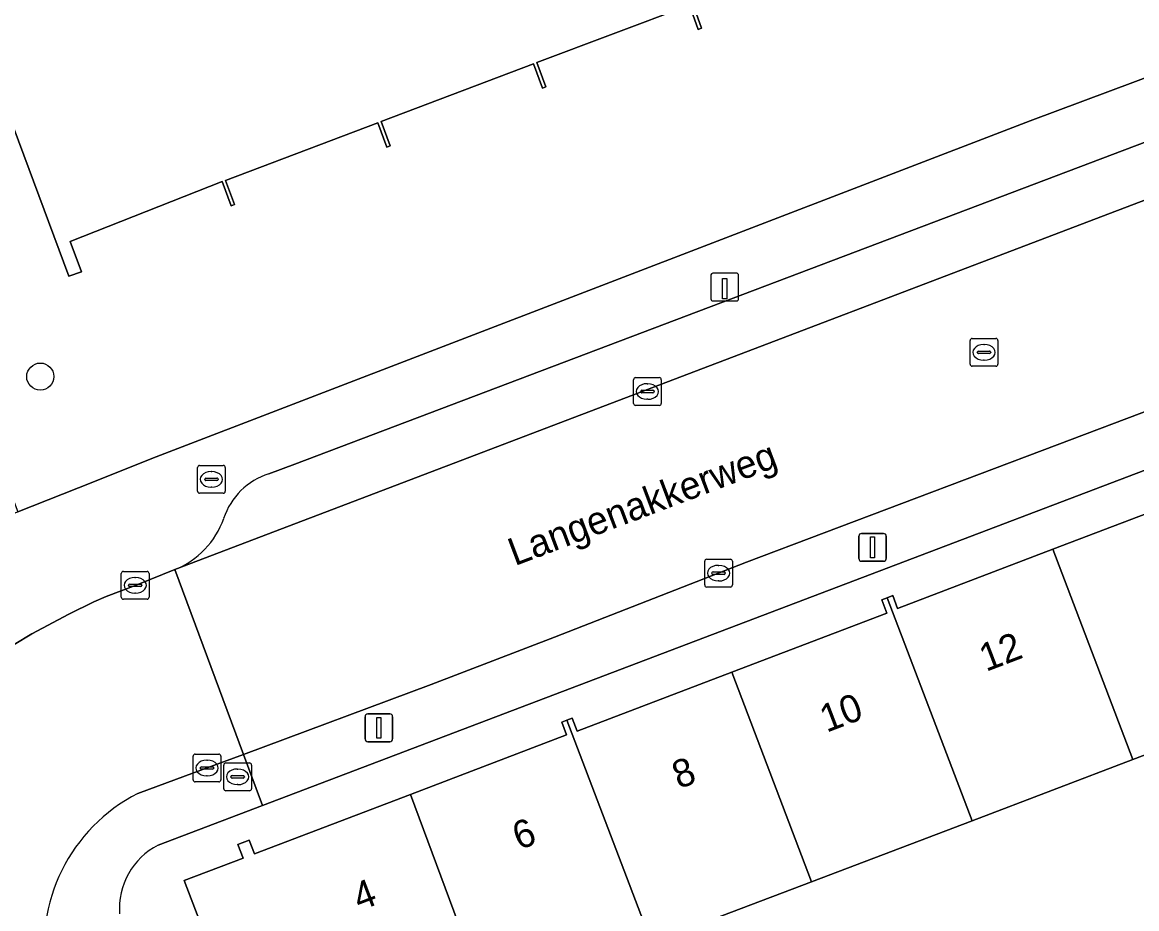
# Model space of a CAD drawing. Extents: x 159262 to 160143, y 383399 to 384319.
# Drawn here: x 159354.79 to 159394.93, y 383878.17 to 383910.07 of the extents above; entities that cross this region are included whole.
import ezdxf

# ---------------------------------------------------------------- set-up
doc = ezdxf.new("R2010")
doc.units = 0
for name, color, linetype in [('IMGEO_Boom', 7, 'Continuous'), ('IMGEO_Brandkraan', 7, 'Continuous'), ('IMGEO_Erf', 7, 'Continuous'), ('IMGEO_Kolk', 7, 'Continuous'), ('IMGEO_Laadpaal', 7, 'Continuous'), ('IMGEO_Lichtmast', 7, 'Continuous'), ('IMGEO_Openbare_ruimte_label', 7, 'Continuous'), ('IMGEO_Pand', 7, 'Continuous'), ('IMGEO_Pand_nummerreeks', 7, 'Continuous'), ('IMGEO_Parkeervlak_open', 7, 'Continuous'), ('IMGEO_Rijbaan_lokaal_open', 7, 'Continuous'), ('IMGEO_Rioolput', 7, 'Continuous'), ('IMGEO_Voetpad_open', 7, 'Continuous')]:
    doc.layers.add(name, color=color, linetype=linetype)

msp = doc.modelspace()

# ---------------------------------------------------------------- linework, layer by layer
at = {"layer": 'IMGEO_Boom'}
msp.add_circle((159355.441, 383897.316), 0.489, dxfattribs=at)
at = {"layer": 'IMGEO_Brandkraan'}
for p, q in [((159361.103, 383893.192), (159361.103, 383894.044)), ((159361.178, 383894.118), (159362.03, 383894.118)), ((159361.591, 383893.898), (159361.616, 383893.898)), ((159362.104, 383894.044), (159362.104, 383893.192)), ((159361.362, 383893.612), (159361.362, 383893.624)), ((159361.8, 383893.575), (159361.402, 383893.575)), ((159361.405, 383893.661), (159361.803, 383893.661)), ((159361.846, 383893.624), (159361.846, 383893.612)), ((159362.03, 383893.118), (159361.178, 383893.118)), ((159361.614, 383893.338), (159361.589, 383893.338)), ((159362.122, 383883.413), (159362.974, 383883.413)), ((159362.047, 383882.487), (159362.047, 383883.339)), ((159362.535, 383883.193), (159362.56, 383883.193)), ((159363.048, 383883.339), (159363.048, 383882.487)), ((159362.306, 383882.907), (159362.306, 383882.919)), ((159362.744, 383882.87), (159362.346, 383882.87)), ((159362.349, 383882.956), (159362.747, 383882.956)), ((159362.558, 383882.633), (159362.533, 383882.633)), ((159362.79, 383882.919), (159362.79, 383882.907)), ((159362.974, 383882.413), (159362.122, 383882.413))]:
    msp.add_line(p, q, dxfattribs=at)
for points in [[(159361.103, 383893.192), (159361.103, 383894.044)], [(159361.178, 383894.118), (159362.03, 383894.118)], [(159362.104, 383894.044), (159362.104, 383893.192)], [(159362.03, 383893.118), (159361.178, 383893.118)], [(159362.122, 383883.413), (159362.974, 383883.413)], [(159362.047, 383882.487), (159362.047, 383883.339)], [(159363.048, 383883.339), (159363.048, 383882.487)], [(159362.974, 383882.413), (159362.122, 383882.413)]]:
    msp.add_lwpolyline(points, dxfattribs=at)
for centre, radius, start, end in [((159361.18, 383894.042), 0.0765, 91.552, 178.448), ((159361.18, 383894.042), 0.0765, 91.552, 178.448), ((159362.028, 383894.042), 0.0765, 1.552, 88.448), ((159362.028, 383894.042), 0.0765, 1.552, 88.448), ((159361.402, 383893.621), 0.0403, 85.8775, 175.7526), ((159361.399, 383893.611), 0.0366, 178.938, 274.7102), ((159361.803, 383893.618), 0.043, 264.8664, 352.4533), ((159361.807, 383893.623), 0.0386, 1.7309, 96.639), ((159361.18, 383893.194), 0.0765, 181.552, 268.448), ((159361.18, 383893.194), 0.0765, 181.552, 268.448), ((159362.028, 383893.194), 0.0765, 271.552, 358.448), ((159362.028, 383893.194), 0.0765, 271.552, 358.448), ((159362.124, 383883.337), 0.0765, 91.552, 178.448), ((159362.124, 383883.337), 0.0765, 91.552, 178.448), ((159362.972, 383883.337), 0.0765, 1.552, 88.448), ((159362.972, 383883.337), 0.0765, 1.552, 88.448), ((159362.346, 383882.916), 0.0403, 85.8775, 175.7526), ((159362.343, 383882.906), 0.0366, 178.938, 274.7102), ((159362.747, 383882.913), 0.043, 264.8664, 352.4533), ((159362.751, 383882.918), 0.0386, 1.7309, 96.639), ((159362.124, 383882.489), 0.0765, 181.552, 268.448), ((159362.124, 383882.489), 0.0765, 181.552, 268.448), ((159362.972, 383882.489), 0.0765, 271.552, 358.448), ((159362.972, 383882.489), 0.0765, 271.552, 358.448)]:
    msp.add_arc(centre, radius, start, end, dxfattribs=at)
for centre, major_axis, ratio, start_param, end_param in [((159361.59, 383893.618), (-0.387, 0.002), 0.722429, 4.712389, 7.853982), ((159361.615, 383893.618), (-0.39, 0.002), 0.717154, 1.570796, 4.712389), ((159362.534, 383882.913), (-0.387, 0.002), 0.722429, 4.712389, 7.853982), ((159362.559, 383882.913), (-0.39, 0.002), 0.717154, 1.570796, 4.712389)]:
    msp.add_ellipse(centre, major_axis=major_axis, ratio=ratio, start_param=start_param, end_param=end_param, dxfattribs=at)
at = {"layer": 'IMGEO_Erf'}
for points in [[(159344.204, 383933.471), (159339.87, 383931.849), (159348.323, 383909.525), (159348.27, 383909.245), (159354.634, 383892.446), (159357.328, 383893.521), (159359.454, 383894.369), (159391.087, 383906.525), (159403.464, 383911.157), (159412.277, 383914.472)], [(159378.937, 383910.729), (159379.258, 383909.858), (159379.136, 383909.813), (159378.815, 383910.684), (159373.326, 383908.62), (159373.651, 383907.742), (159373.531, 383907.692), (159373.204, 383908.575), (159367.722, 383906.498), (159368.044, 383905.618), (159367.917, 383905.574), (159367.6, 383906.453), (159362.107, 383904.377), (159362.437, 383903.507), (159362.313, 383903.46), (159361.985, 383904.332), (159356.515, 383902.181), (159356.921, 383901.091), (159356.474, 383900.927), (159352.679, 383911.103)], [(159417.717, 383902.495), (159363.447, 383881.885), (159359.686, 383880.457)], [(159364.276, 383875.969), (159362.156, 383875.163), (159360.626, 383879.181), (159362.747, 383879.988), (159362.561, 383880.477), (159362.965, 383880.63), (159363.151, 383880.142), (159368.772, 383882.281), (159374.393, 383884.42), (159374.219, 383884.877), (159374.408, 383884.949), (159374.596, 383885.02), (159374.772, 383884.558), (159380.35, 383886.681), (159385.928, 383888.803), (159385.746, 383889.283), (159385.945, 383889.359), (159386.143, 383889.434), (159386.317, 383888.976), (159391.905, 383891.102), (159397.497, 383893.23)], [(159400.601, 383885.744), (159394.782, 383883.533), (159388.995, 383881.334), (159383.217, 383879.139), (159377.449, 383876.947), (159373.982, 383875.629), (159376.97, 383867.779), (159380.322, 383869.052), (159384.098, 383870.487), (159384.955, 383868.233), (159388.968, 383869.781), (159388.161, 383871.871), (159391.972, 383873.342), (159395.894, 383874.856)]]:
    msp.add_lwpolyline(points, dxfattribs=at)
msp.add_arc((159360.856, 383878.173), 2.567, 117.1268, 184.3488, dxfattribs=at)
at = {"layer": 'IMGEO_Kolk'}
for p, q in [((159376.804, 383896.354), (159376.804, 383897.206)), ((159376.879, 383897.28), (159377.731, 383897.28)), ((159377.292, 383897.06), (159377.317, 383897.06)), ((159377.805, 383897.206), (159377.805, 383896.354)), ((159377.063, 383896.774), (159377.063, 383896.786)), ((159377.501, 383896.737), (159377.103, 383896.737)), ((159377.106, 383896.823), (159377.504, 383896.823)), ((159377.547, 383896.786), (159377.547, 383896.774)), ((159377.731, 383896.28), (159376.879, 383896.28)), ((159377.315, 383896.5), (159377.29, 383896.5)), ((159379.367, 383889.817), (159379.367, 383890.669)), ((159379.442, 383890.743), (159380.294, 383890.743)), ((159380.368, 383890.669), (159380.368, 383889.817)), ((159358.359, 383889.379), (159358.359, 383890.231)), ((159358.434, 383890.305), (159359.286, 383890.305)), ((159359.36, 383890.231), (159359.36, 383889.379)), ((159379.626, 383890.237), (159379.626, 383890.249)), ((159379.669, 383890.286), (159380.067, 383890.286)), ((159379.855, 383890.523), (159379.88, 383890.523)), ((159380.11, 383890.249), (159380.11, 383890.237)), ((159358.661, 383889.848), (159359.059, 383889.848)), ((159358.847, 383890.085), (159358.872, 383890.085)), ((159380.064, 383890.2), (159379.666, 383890.2)), ((159379.878, 383889.963), (159379.853, 383889.963)), ((159358.618, 383889.799), (159358.618, 383889.811)), ((159359.056, 383889.762), (159358.658, 383889.762)), ((159358.87, 383889.525), (159358.845, 383889.525)), ((159359.102, 383889.811), (159359.102, 383889.799)), ((159380.294, 383889.743), (159379.442, 383889.743)), ((159359.286, 383889.305), (159358.434, 383889.305)), ((159360.945, 383882.805), (159360.945, 383883.657)), ((159361.02, 383883.731), (159361.872, 383883.731)), ((159361.433, 383883.511), (159361.458, 383883.511)), ((159361.946, 383883.657), (159361.946, 383882.805)), ((159361.204, 383883.225), (159361.204, 383883.237)), ((159361.642, 383883.188), (159361.244, 383883.188)), ((159361.247, 383883.274), (159361.645, 383883.274)), ((159361.688, 383883.237), (159361.688, 383883.225)), ((159361.872, 383882.731), (159361.02, 383882.731)), ((159361.456, 383882.951), (159361.431, 383882.951))]:
    msp.add_line(p, q, dxfattribs=at)
for points in [[(159376.804, 383896.354), (159376.804, 383897.206)], [(159376.879, 383897.28), (159377.731, 383897.28)], [(159377.805, 383897.206), (159377.805, 383896.354)], [(159377.731, 383896.28), (159376.879, 383896.28)], [(159379.367, 383889.817), (159379.367, 383890.669)], [(159379.442, 383890.743), (159380.294, 383890.743)], [(159380.368, 383890.669), (159380.368, 383889.817)], [(159358.359, 383889.379), (159358.359, 383890.231)], [(159358.434, 383890.305), (159359.286, 383890.305)], [(159359.36, 383890.231), (159359.36, 383889.379)], [(159380.294, 383889.743), (159379.442, 383889.743)], [(159359.286, 383889.305), (159358.434, 383889.305)], [(159360.945, 383882.805), (159360.945, 383883.657)], [(159361.02, 383883.731), (159361.872, 383883.731)], [(159361.946, 383883.657), (159361.946, 383882.805)], [(159361.872, 383882.731), (159361.02, 383882.731)]]:
    msp.add_lwpolyline(points, dxfattribs=at)
for centre, radius, start, end in [((159376.881, 383897.204), 0.0765, 91.552, 178.448), ((159376.881, 383897.204), 0.0765, 91.552, 178.448), ((159377.729, 383897.204), 0.0765, 1.552, 88.448), ((159377.729, 383897.204), 0.0765, 1.552, 88.448), ((159377.103, 383896.783), 0.0403, 85.8775, 175.7526), ((159377.1, 383896.773), 0.0366, 178.938, 274.7102), ((159377.504, 383896.78), 0.043, 264.8664, 352.4533), ((159377.508, 383896.785), 0.0386, 1.7309, 96.639), ((159376.881, 383896.356), 0.0765, 181.552, 268.448), ((159376.881, 383896.356), 0.0765, 181.552, 268.448), ((159377.729, 383896.356), 0.0765, 271.552, 358.448), ((159377.729, 383896.356), 0.0765, 271.552, 358.448), ((159379.444, 383890.667), 0.0765, 91.552, 178.448), ((159379.444, 383890.667), 0.0765, 91.552, 178.448), ((159380.292, 383890.667), 0.0765, 1.552, 88.448), ((159380.292, 383890.667), 0.0765, 1.552, 88.448), ((159358.436, 383890.229), 0.0765, 91.552, 178.448), ((159358.436, 383890.229), 0.0765, 91.552, 178.448), ((159359.284, 383890.229), 0.0765, 1.552, 88.448), ((159359.284, 383890.229), 0.0765, 1.552, 88.448), ((159379.666, 383890.246), 0.0403, 85.8775, 175.7526), ((159379.663, 383890.236), 0.0366, 178.938, 274.7102), ((159380.067, 383890.243), 0.043, 264.8664, 352.4533), ((159380.071, 383890.248), 0.0386, 1.7309, 96.639), ((159358.658, 383889.808), 0.0403, 85.8775, 175.7526), ((159359.063, 383889.81), 0.0386, 1.7309, 96.639), ((159379.444, 383889.819), 0.0765, 181.552, 268.448), ((159379.444, 383889.819), 0.0765, 181.552, 268.448), ((159380.292, 383889.819), 0.0765, 271.552, 358.448), ((159380.292, 383889.819), 0.0765, 271.552, 358.448), ((159358.655, 383889.798), 0.0366, 178.938, 274.7102), ((159359.059, 383889.805), 0.043, 264.8664, 352.4533), ((159358.436, 383889.381), 0.0765, 181.552, 268.448), ((159358.436, 383889.381), 0.0765, 181.552, 268.448), ((159359.284, 383889.381), 0.0765, 271.552, 358.448), ((159359.284, 383889.381), 0.0765, 271.552, 358.448), ((159361.022, 383883.655), 0.0765, 91.552, 178.448), ((159361.022, 383883.655), 0.0765, 91.552, 178.448), ((159361.87, 383883.655), 0.0765, 1.552, 88.448), ((159361.87, 383883.655), 0.0765, 1.552, 88.448), ((159361.244, 383883.234), 0.0403, 85.8775, 175.7526), ((159361.241, 383883.224), 0.0366, 178.938, 274.7102), ((159361.645, 383883.231), 0.043, 264.8664, 352.4533), ((159361.649, 383883.236), 0.0386, 1.7309, 96.639), ((159361.022, 383882.807), 0.0765, 181.552, 268.448), ((159361.022, 383882.807), 0.0765, 181.552, 268.448), ((159361.87, 383882.807), 0.0765, 271.552, 358.448), ((159361.87, 383882.807), 0.0765, 271.552, 358.448)]:
    msp.add_arc(centre, radius, start, end, dxfattribs=at)
for centre, major_axis, ratio, start_param, end_param in [((159377.291, 383896.78), (-0.387, 0.002), 0.722429, 4.712389, 7.853982), ((159377.316, 383896.78), (-0.39, 0.002), 0.717154, 1.570796, 4.712389), ((159379.854, 383890.243), (-0.387, 0.002), 0.722429, 4.712389, 7.853982), ((159379.879, 383890.243), (-0.39, 0.002), 0.717154, 1.570796, 4.712389), ((159358.846, 383889.805), (-0.387, 0.002), 0.722429, 4.712389, 7.853982), ((159358.871, 383889.805), (-0.39, 0.002), 0.717154, 1.570796, 4.712389), ((159361.432, 383883.231), (-0.387, 0.002), 0.722429, 4.712389, 7.853982), ((159361.457, 383883.231), (-0.39, 0.002), 0.717154, 1.570796, 4.712389)]:
    msp.add_ellipse(centre, major_axis=major_axis, ratio=ratio, start_param=start_param, end_param=end_param, dxfattribs=at)
at = {"layer": 'IMGEO_Laadpaal'}
for p, q in [((159379.589, 383900.954), (159379.589, 383900.113)), ((159379.589, 383900.954), (159379.589, 383900.113)), ((159380.505, 383901.038), (159379.664, 383901.038)), ((159380.505, 383901.038), (159379.664, 383901.038)), ((159380.589, 383900.122), (159380.589, 383900.963)), ((159380.589, 383900.122), (159380.589, 383900.963)), ((159379.673, 383900.038), (159380.514, 383900.038)), ((159379.673, 383900.038), (159380.514, 383900.038))]:
    msp.add_line(p, q, dxfattribs=at)
msp.add_lwpolyline([(159380.004, 383900.851), (159380.164, 383900.851), (159380.164, 383900.118), (159380.004, 383900.118), (159380.004, 383900.851)], dxfattribs=at)
for centre, start, end in [((159379.667, 383900.96), 92.4484, 184.2845), ((159379.667, 383900.96), 92.4484, 184.2845), ((159380.511, 383900.96), 2.4484, 94.2845), ((159380.511, 383900.96), 2.4484, 94.2845), ((159379.667, 383900.116), 182.4484, 274.2845), ((159379.667, 383900.116), 182.4484, 274.2845), ((159380.511, 383900.116), 272.4484, 4.2845), ((159380.511, 383900.116), 272.4484, 4.2845)]:
    msp.add_arc(centre, 0.0779, start, end, dxfattribs=at)
at = {"layer": 'IMGEO_Lichtmast'}
for p, q in [((159384.919, 383890.772), (159384.919, 383891.572)), ((159384.919, 383891.572), (159384.919, 383890.772)), ((159385.019, 383891.672), (159385.809, 383891.672)), ((159385.809, 383891.672), (159385.019, 383891.672)), ((159385.909, 383891.572), (159385.909, 383890.772)), ((159385.909, 383890.772), (159385.909, 383891.572)), ((159385.809, 383890.672), (159385.019, 383890.672)), ((159385.019, 383890.672), (159385.809, 383890.672)), ((159367.137, 383884.278), (159367.137, 383885.078)), ((159367.137, 383885.078), (159367.137, 383884.278)), ((159367.237, 383885.178), (159368.027, 383885.178)), ((159368.027, 383885.178), (159367.237, 383885.178)), ((159368.127, 383885.078), (159368.127, 383884.278)), ((159368.127, 383884.278), (159368.127, 383885.078)), ((159368.027, 383884.178), (159367.237, 383884.178)), ((159367.237, 383884.178), (159368.027, 383884.178))]:
    msp.add_line(p, q, dxfattribs=at)
for points in [[(159385.339, 383891.547), (159385.489, 383891.547), (159385.489, 383890.797), (159385.339, 383890.797), (159385.339, 383891.547)], [(159367.557, 383885.053), (159367.707, 383885.053), (159367.707, 383884.303), (159367.557, 383884.303), (159367.557, 383885.053)]]:
    msp.add_lwpolyline(points, dxfattribs=at)
for centre, start, end in [((159385.019, 383891.572), 90, 180), ((159385.019, 383891.572), 90, 180), ((159385.809, 383891.572), 0, 90), ((159385.809, 383891.572), 360, 90), ((159385.019, 383890.772), 180, 270), ((159385.019, 383890.772), 180, 270), ((159385.809, 383890.772), 270, 0), ((159385.809, 383890.772), 270, 0), ((159367.237, 383885.078), 90, 180), ((159367.237, 383885.078), 90, 180), ((159368.027, 383885.078), 0, 90), ((159368.027, 383885.078), 360, 90), ((159367.237, 383884.278), 180, 270), ((159367.237, 383884.278), 180, 270), ((159368.027, 383884.278), 270, 0), ((159368.027, 383884.278), 270, 0)]:
    msp.add_arc(centre, 0.1, start, end, dxfattribs=at)
at = {"layer": 'IMGEO_Pand'}
msp.add_lwpolyline([(159352.679, 383911.103), (159356.474, 383900.927), (159356.921, 383901.091), (159356.515, 383902.181), (159361.985, 383904.332), (159362.313, 383903.46), (159362.437, 383903.507), (159362.107, 383904.377), (159367.6, 383906.453), (159367.917, 383905.574), (159368.044, 383905.618), (159367.722, 383906.498), (159373.204, 383908.575), (159373.531, 383907.692), (159373.651, 383907.742), (159373.326, 383908.62), (159378.815, 383910.684), (159379.136, 383909.813), (159379.258, 383909.858), (159378.937, 383910.729)], dxfattribs=at)
for points in [[(159400.601, 383885.744), (159397.57, 383893.72), (159397.343, 383893.634), (159397.497, 383893.23), (159391.905, 383891.102), (159394.782, 383883.533)], [(159385.945, 383889.359), (159388.995, 383881.334), (159394.782, 383883.533), (159391.905, 383891.102), (159386.317, 383888.976), (159386.143, 383889.434)], [(159380.35, 383886.681), (159383.217, 383879.139), (159388.995, 383881.334), (159385.945, 383889.359), (159385.746, 383889.283), (159385.928, 383888.803)], [(159380.35, 383886.681), (159374.772, 383884.558), (159374.596, 383885.02), (159374.408, 383884.949), (159377.449, 383876.947), (159383.217, 383879.139)], [(159374.408, 383884.949), (159374.219, 383884.877), (159374.393, 383884.42), (159368.772, 383882.281), (159371.584, 383874.719), (159371.589, 383874.706), (159374.381, 383867.004), (159374.446, 383866.82), (159375.271, 383864.492), (159381.185, 383866.779), (159380.882, 383867.577), (159380.322, 383869.052), (159376.97, 383867.779), (159373.982, 383875.629), (159377.449, 383876.947)], [(159368.772, 383882.281), (159363.151, 383880.142), (159362.965, 383880.63), (159362.561, 383880.477), (159362.747, 383879.988), (159360.626, 383879.181), (159362.156, 383875.163), (159364.276, 383875.969), (159365.755, 383872.084), (159366.138, 383872.23), (159365.998, 383872.596), (159368.849, 383873.679), (159371.584, 383874.719)]]:
    msp.add_lwpolyline(points, close=True, dxfattribs=at)
at = {"layer": 'IMGEO_Parkeervlak_open'}
for points in [[(159405.054, 383909.537), (159398.907, 383907.143), (159364.612, 383894.169), (159363.675, 383893.818)], [(159360.29, 383890.372), (159408.89, 383908.872)]]:
    msp.add_lwpolyline(points, dxfattribs=at)
for centre, radius, start, end in [((159364.424, 383891.427), 2.506, 107.4042, 161.746), ((159359.133, 383893.233), 3.086, 292.023, 340.6859)]:
    msp.add_arc(centre, radius, start, end, dxfattribs=at)
at = {"layer": 'IMGEO_Rijbaan_lokaal_open'}
for points in [[(159410.756, 383903.776), (159411.474, 383904.062), (159409.489, 383909.098), (159408.89, 383908.872), (159360.29, 383890.372), (159362.763, 383883.722), (159369.522, 383886.236), (159373.965, 383887.945), (159380.876, 383890.636), (159392.067, 383894.857), (159402.096, 383898.646)], [(159358.957, 383882.315), (159361.319, 383883.185), (159362.763, 383883.722), (159360.29, 383890.372), (159358.892, 383889.815), (159357.811, 383889.405), (159357.368, 383889.209), (159356.469, 383888.77), (159355.133, 383888.057), (159353.851, 383887.296)]]:
    msp.add_lwpolyline(points, dxfattribs=at)
msp.add_arc((159361.741, 383876.818), 6.162, 116.8603, 190.6332, dxfattribs=at)
at = {"layer": 'IMGEO_Rioolput'}
for p, q in [((159389.002, 383898.691), (159389.854, 383898.691)), ((159388.927, 383897.765), (159388.927, 383898.617)), ((159389.415, 383898.471), (159389.44, 383898.471)), ((159389.928, 383898.617), (159389.928, 383897.765)), ((159389.186, 383898.185), (159389.186, 383898.197)), ((159389.624, 383898.148), (159389.226, 383898.148)), ((159389.229, 383898.234), (159389.627, 383898.234)), ((159389.438, 383897.911), (159389.413, 383897.911)), ((159389.67, 383898.197), (159389.67, 383898.185)), ((159389.854, 383897.691), (159389.002, 383897.691))]:
    msp.add_line(p, q, dxfattribs=at)
for points in [[(159389.002, 383898.691), (159389.854, 383898.691)], [(159388.927, 383897.765), (159388.927, 383898.617)], [(159389.928, 383898.617), (159389.928, 383897.765)], [(159389.854, 383897.691), (159389.002, 383897.691)]]:
    msp.add_lwpolyline(points, dxfattribs=at)
for centre, radius, start, end in [((159389.004, 383898.615), 0.0765, 91.552, 178.448), ((159389.004, 383898.615), 0.0765, 91.552, 178.448), ((159389.852, 383898.615), 0.0765, 1.552, 88.448), ((159389.852, 383898.615), 0.0765, 1.552, 88.448), ((159389.226, 383898.194), 0.0403, 85.8775, 175.7526), ((159389.223, 383898.184), 0.0366, 178.938, 274.7102), ((159389.627, 383898.191), 0.043, 264.8664, 352.4533), ((159389.631, 383898.196), 0.0386, 1.7309, 96.639), ((159389.004, 383897.767), 0.0765, 181.552, 268.448), ((159389.004, 383897.767), 0.0765, 181.552, 268.448), ((159389.852, 383897.767), 0.0765, 271.552, 358.448), ((159389.852, 383897.767), 0.0765, 271.552, 358.448)]:
    msp.add_arc(centre, radius, start, end, dxfattribs=at)
for centre, major_axis, ratio, start_param, end_param in [((159389.414, 383898.191), (-0.387, 0.002), 0.722429, 4.712389, 7.853982), ((159389.439, 383898.191), (-0.39, 0.002), 0.717154, 1.570796, 4.712389)]:
    msp.add_ellipse(centre, major_axis=major_axis, ratio=ratio, start_param=start_param, end_param=end_param, dxfattribs=at)
at = {"layer": 'IMGEO_Voetpad_open'}
for points in [[(159412.277, 383914.472), (159403.464, 383911.157), (159391.087, 383906.525), (159359.454, 383894.369), (159357.328, 383893.521), (159354.634, 383892.446), (159352.307, 383891.408)], [(159363.675, 383893.818), (159364.612, 383894.169), (159398.907, 383907.143), (159405.054, 383909.537)], [(159408.31, 383901.097), (159407.335, 383900.738), (159402.096, 383898.646), (159392.067, 383894.857), (159380.876, 383890.636), (159373.965, 383887.945), (159369.522, 383886.236), (159362.763, 383883.722), (159363.447, 383881.885), (159417.717, 383902.495)], [(159353.851, 383887.296), (159355.133, 383888.057), (159356.469, 383888.77), (159357.368, 383889.209), (159357.811, 383889.405), (159358.892, 383889.815), (159360.29, 383890.372)], [(159359.686, 383880.457), (159363.447, 383881.885), (159362.763, 383883.722), (159361.319, 383883.185), (159358.957, 383882.315)]]:
    msp.add_lwpolyline(points, dxfattribs=at)
for centre, radius, start, end in [((159364.424, 383891.427), 2.506, 107.4042, 161.746), ((159359.133, 383893.233), 3.086, 292.023, 340.6859), ((159361.741, 383876.818), 6.162, 116.8603, 190.6332), ((159360.856, 383878.173), 2.567, 117.1268, 184.3488)]:
    msp.add_arc(centre, radius, start, end, dxfattribs=at)

# ---------------------------------------------------------------- texts
at = {"layer": 'IMGEO_Openbare_ruimte_label'}
msp.add_text('Langenakkerweg', height=1, rotation=20.6835, dxfattribs=at).set_placement((159372.529, 383890.493))
at = {"layer": 'IMGEO_Pand_nummerreeks'}
for s, rotation, p in [('12', 20.8903, (159389.498, 383886.687)), ('10', 20.8903, (159383.755, 383884.495)), ('8', 20.8903, (159378.437, 383882.466)), ('6', 20.89, (159372.685, 383880.27)), ('4', 20.89, (159366.937, 383878.077))]:
    msp.add_text(s, height=1, rotation=rotation, dxfattribs=at).set_placement(p)

doc.saveas('drawing.dxf')
